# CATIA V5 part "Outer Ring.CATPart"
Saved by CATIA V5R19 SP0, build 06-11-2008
Part number: Outer Ring
Bounding box of the stored display mesh (mm): x -99.819 to 99.819, y 0 to 50, z -100 to 100
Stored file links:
  D:\Shriniwas\v5_r19\c16_CAT_v5r19\c16_Part\Roll curve Joint\tut_4 _final\Outer Ring.CATPart
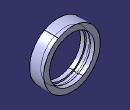
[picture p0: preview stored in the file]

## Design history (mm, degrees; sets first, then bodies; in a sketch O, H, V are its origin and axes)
Body1 (main body)
  Sketch1 on yz-plane, origin (0, 0, 0), H (0, 1, 0), V (0, 0, 1)
    point P1 (0, 80)
    line L1 (0, 80) -> (0, 100)
    line L2 (0, 100) -> (50, 100)
    line L3 (50, 100) -> (50, 80)
    line L4 (50, 80) -> (35, 80)
    line L5 (35, 80) -> (35, 85)
    line L6 (35, 85) -> (15, 85)
    line L7 (15, 85) -> (15, 80)
    point P8 (15, 80)
    line L8 (15, 80) -> (0, 80)
    point P9 (0, 80)
    distance H L8 = 80
    length L2 = 50
    length L5 = 5
    length L8 = 15
    length L4 = 15
    length L1 = 20
    coincidence: P1 V, P8 L4, P9 V, P9 P1
    vertical: L1 V, L3 V, L5 V, L7 V
    horizontal: L2 H, L4 H, L6 H, L8 H
  Shaft1: profile Sketch1, axis Sketch1.H, angle 360
  Plane1: type Offset, Offset 10, RefPlane face of Shaft1 from Sketch1.L5, reversed
  Sketch2 on Plane1, origin (0, 25, 0), H (-1, 0, 0), V (0, 0, 1)
    projected circle E1 centre (0, 0) radius 85 from edge [face of Shaft1 from Sketch1.L6 | face of Shaft1 from Sketch1.L7]
  Point1: type OnCurve, Support Sketch2, Length 282.187, RefPoint {extremum Reference Sketch2, Direction (1, 2, 3)}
